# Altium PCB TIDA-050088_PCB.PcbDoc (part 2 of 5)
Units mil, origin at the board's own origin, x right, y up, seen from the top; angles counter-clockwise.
Board outline 8500 x 7000 mil, 8 copper layers (Top Layer, Layer 1 - GND, Signal Layer 2, Layer 3 - GND, Layer 4 - Power, Signal Layer 5, Layer 6 - GND, Bottom Layer), stack 61.6 mil thick; 537 components, 169 nets, 1427 pads, 1411 vias.
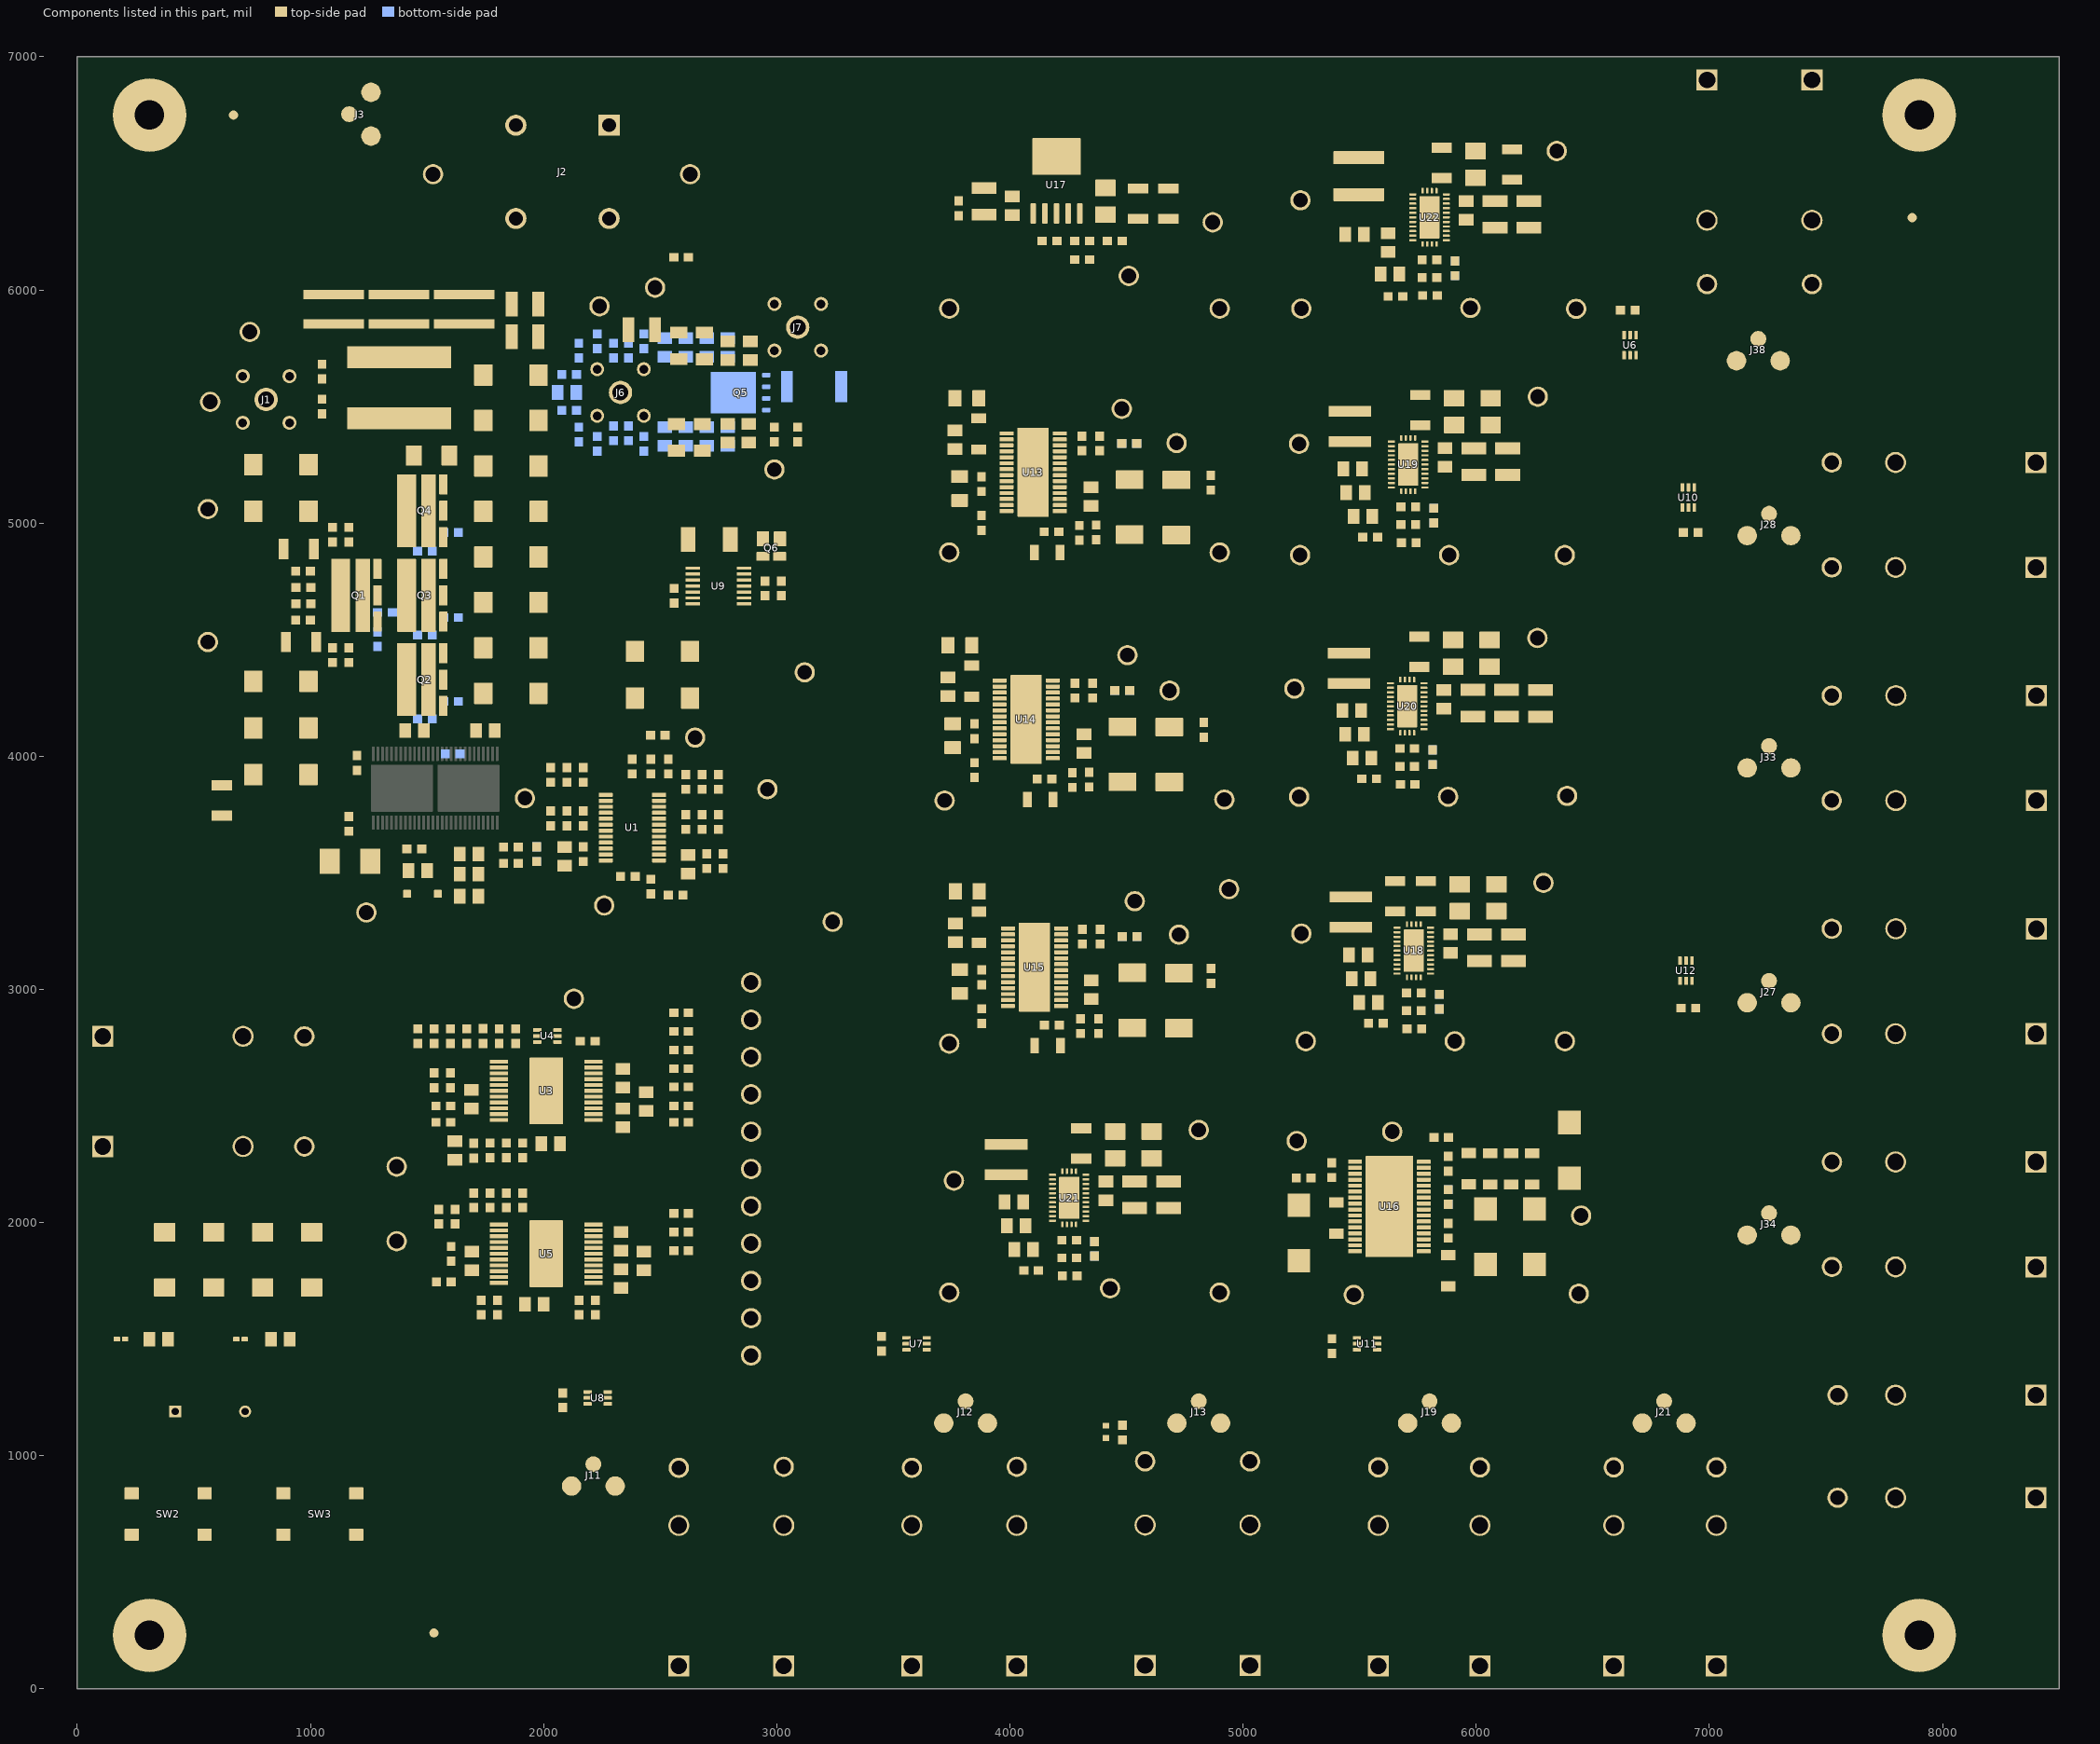
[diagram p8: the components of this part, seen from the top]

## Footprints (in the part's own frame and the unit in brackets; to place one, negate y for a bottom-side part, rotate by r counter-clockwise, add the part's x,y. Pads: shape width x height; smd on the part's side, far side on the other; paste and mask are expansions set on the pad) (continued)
DAP0032F-MFG [mm]
  rrect22% 1.5x0.45 smd paste+0 mask+0: 1(-3.75,4.875) 2(-3.75,4.225) 3(-3.75,3.575) 4(-3.75,2.925) 5(-3.75,2.275) 6(-3.75,1.625) 7(-3.75,0.975) 8(-3.75,0.325) 9(-3.75,-0.325) 10(-3.75,-0.975) 11(-3.75,-1.625) 12(-3.75,-2.275) 13(-3.75,-2.925) 14(-3.75,-3.575) 15(-3.75,-4.225) 16(-3.75,-4.875) 17(3.75,-4.875) 18(3.75,-4.225) 19(3.75,-3.575) 20(3.75,-2.925) 21(3.75,-2.275) 22(3.75,-1.625) 23(3.75,-0.975) 24(3.75,-0.325) 25(3.75,0.325) 26(3.75,0.975) 27(3.75,1.625) 28(3.75,2.275) 29(3.75,2.925) 30(3.75,3.575) 31(3.75,4.225) 32(3.75,4.875)
  rrect2% 5.2x11 smd paste-1000 mask-1000: 33(0,0)
  silkscreen extent -5.2,-5.55 3.1,5.55, body extent -4.6,-5.8 4.6,5.8, height 0.25
DCK0006A-MFG [mm]
  rrect25% 0.9x0.4 smd paste-1000 mask+0: 1(-1.1,0.65) 2(-1.1,0) 3(-1.1,-0.65) 4(1.1,-0.65) 5(1.1,0) 6(1.1,0.65)
  silkscreen extent -2.23,-1.07 0.27,1.07, body extent -1.65,-1.33 1.65,1.33, height 0.25
DCQ0006A-MFG [mm]
  rrect17% 2.2x0.6 smd paste-1000 mask+0: 1(-3.1,2.54) 2(-3.1,1.27) 3(-3.1,0) 4(-3.1,-1.27) 5(-3.1,-2.54)
  rrect3% 4x5.3 smd paste-1000 mask-1000: 6(3.1,0)
  silkscreen extent -4.9,-3.27 1.78,3.27, body extent -4.3,-3.37 5.2,3.37, height 0.25
DQH0008A [mm] "TI"
  rrect39% 0.91x0.51 smd paste-0.05 mask-0.05: 1(-2.795,1.905) 2(-2.795,0.635) 3(-2.795,-0.635) 4(-2.795,-1.905) 5(2.795,-1.905) 6(2.795,-0.635) 7(2.795,0.635) 8(2.795,1.905)
  rrect9% 1.14x1.23 on Bottom Paste: 9(-1.06,-1.43) 9(-1.06,0) 9(-1.06,1.43) 9(0.28,-1.43) 9(0.28,0) 9(0.28,1.43) 9(1.62,-1.43) 9(1.62,0) 9(1.62,1.43)
  rrect2% 4.02x4.42 on Bottom Solder: 9(0.38,0)
  rrect2% 4.93x4.52 smd paste-3 mask-3: 9(0.786,0)
  silkscreen extent -3.18,-2.68 3.18,2.68, body extent -3.05,-2.55 3.05,2.55, height 1.06
FCC_disclaimer [mil]
Fiducial10-20 [mm]
  round 1 smd mask+0.5: 1(0,0)
  Top Layer keep-out circle w1.178: c0,0 r0.5
FP-1929517_HDR2-MFG [mm]
  round 2.3 hole 1.5 paste-2539.97 mask+0: 1(-5.18,7.82) 2(4.98,7.82) 2(4.98,-2.34)
  rect 2.3x2.3 hole 1.5 paste-2539.97 mask+0: 1(-5.18,-2.34)
  body extent -10.36,-11.2 10.36,11.2, height 0.25
FP-430182050816_SMT_SW_6MM2_6MM2-MFG [mm]
  rrect8% 1.55x1.3 smd paste+0 mask+0: 1(-3.975,2.25) 2(-3.975,-2.25) 3(3.975,2.25) 4(3.975,-2.25)
  silkscreen extent -5.42,-3.2 3.2,3.2, body extent -4.85,-3.3 4.85,3.3, height 0.25
FP-60312102114405_CONN_SMA-MFG [mm]
  round 1.73 smd paste+0 mask+0: 1(0,0)
  round 2.115 smd paste+0 mask+0: 2(-2.38,-2.385) 3(2.38,-2.385)
  Top Layer region: 3.555,-3.56 3.555,3.56 1.205,3.56 1.205,1.652 1.823,0.927 2.045,0 1.823,-0.927 1.205,-1.652 1.205,-1.652 1.205,-3.56
  Top Layer region: -3.555,-3.56 -3.555,3.56 -1.205,3.56 -1.205,1.652 -1.823,0.927 -2.045,0 -1.823,-0.927 -1.205,-1.652 -1.205,-1.652 -1.205,-3.56
  silkscreen extent -0.83,-3.27 0.83,3.27, body extent -3.66,-3.66 3.66,3.66, height 0.25
FP-A6TN-1104_PTH_SW_7MM50_4MM48-MFG [mm]
  rect 1.3x1.3 hole 0.8 paste-2539.97 mask+0: 1(0,-3.81)
  round 1.3 hole 0.8 paste-2539.97 mask+0: 2(0,3.81)
  body extent -2.59,-4.56 2.59,4.56, height 0.25
FP-BLM18EG221SN1D_0603-MFG [mm]
  rrect15% 0.65x0.7 smd paste+0 mask+0: 1(-0.675,0) 2(0.675,0)
  silkscreen extent -0.87,-0.72 0.87,0.72, body extent -1.1,-0.58 1.1,0.58, height 0.25
FP-BZT52B13-E3-08_SOD123-MFG [mm] "Recommended Land Pattern"
  rrect12% 0.85x0.85 smd paste+0 mask+0: 1(1.675,0) 2(-1.675,0)
  silkscreen extent -2.77,-0.85 1.43,0.85, body extent -2.2,-0.95 2.2,0.95, height 0.25
FP-C1206C225K4RAC7800_1206-MFG [mm] "Recommended Land Pattern"
  rrect11% 0.95x1.7 smd paste+0 mask+0: 1(-1.4,0) 2(1.4,0)
  silkscreen extent -0.55,-0.9 0.55,0.9, body extent -2,-1 2,1, height 0.25
FP-EPC7019GC_FSMD-G-MFG [mm]
  rrect11% 2.184x0.914 smd paste+0 mask+0: 1(2.87,2.286) 2(-2.87,2.286) 5(0,2.286)
  rrect5% 7.95x2.057 smd paste+0 mask+0: 3(0,-1.714)
  rrect6% 7.95x1.575 smd paste+0 mask+0: 4(0,0.686)
  silkscreen extent -4.08,-3.25 4.77,3.25, body extent -4.18,-2.96 4.18,2.96, height 0.25
FP-FBG04N08ACH_FSMD-A-MFG [mm]
  rrect10% 0.965x1.422 smd paste+0 mask+0: 1(-1.118,0.901) 3(-1.118,-0.901)
  rrect7% 1.6x1.346 smd paste+0 mask+0: 2(0.8,0.927) 4(0.8,-0.927)
  silkscreen extent -2.26,-1.97 1.7,1.97, body extent -1.81,-1.81 1.81,1.81, height 0.25
FP-SK5C0A_SMA-MFG [mil]
  rrect6% 67.5x86 smd paste+0 mask+0: 1(-76.25,0) 2(76.25,0)
  silkscreen extent -137,-52 28,52, body extent -114,-56 114,56, height 10
FP-T520X158M2R5ATE015_2917-MFG [mm]
  rrect5% 1.99x2.33 smd paste+0 mask+0: 1(-3.01,0) 2(3.01,0)
  silkscreen extent -3.8,-2.3 4.9,2.3, body extent -4.13,-2.42 4.13,2.42, height 0.25
FP-T521D157M020ATE050_2917-MFG [mm]
  rrect5% 1.99x2.33 smd paste+0 mask+0: 1(3.01,0) 2(-3.01,0)
  silkscreen extent -4.9,-2.3 3.8,2.3, body extent -4.13,-2.42 4.13,2.42, height 0.25
FP-TRME107K020R0035_2917-MFG [mm]
  rrect5% 2x3 smd paste+0 mask+0: 1(-3,0) 2(3,0)
  silkscreen extent -3.75,-2.25 4.87,2.25, body extent -4.1,-2.35 4.1,2.35, height 0.25
HFT0022A-C01-MFG [mm]
  rrect23% 2x0.435 smd paste+0 mask+0: 1(-5.145,3.175) 2(-5.145,2.54) 3(-5.145,1.905) 4(-5.145,1.27) 5(-5.145,0.635) 6(-5.145,0) 7(-5.145,-0.635) 8(-5.145,-1.27) 9(-5.145,-1.905) 10(-5.145,-2.54) 11(-5.145,-3.175) 12(5.145,-3.175) 13(5.145,-2.54) 14(5.145,-1.905) 15(5.145,-1.27) 16(5.145,-0.635) 17(5.145,0) 18(5.145,0.635) 19(5.145,1.27) 20(5.145,1.905) 21(5.145,2.54) 22(5.145,3.175)
  rrect3% 3.62x7.29 smd paste-1000 mask+0: 23(0,0)
  silkscreen extent -6.83,-3.97 3.23,3.97, body extent -6.24,-4.07 6.24,4.07, height 0.25
IEC_HotSurface_Medium [mil]
  silkscreen extent -217,-188 217,188
Keystone5010 [mil] "Keystone Multipurpose loops"
  round 87 hole 63: 1(0,0)
  silkscreen extent -70,-70 70,70, body extent -63,-63 63,62, height 319
Keystone5011 [mil] "Keystone Multipurpose loops"
  round 87 hole 63: 1(0,0)
  silkscreen extent -70,-70 70,70, body extent -63,-63 63,62, height 319
Keystone5012 [mil] "Keystone Multipurpose loops"
  round 87 hole 63: 1(0,0)
  silkscreen extent -70,-70 70,70, body extent -63,-63 63,62, height 319
Keystone_1902C [mil] "Hex Standoff, 4-40 threaded, nylon"
  round 1 on Mech4: 0(0,0)
  body extent -145,-126 146,126, height 501
"NY PMS 440 0025 PH" [mm] "4-40 nylon screw and mounting hole"
  round 8 hole 3.2: 1(0,0)
  body extent -3.3,-3.3 3.3,3.3, height 2.69
PW0014A-MFG [mm]
  rrect29% 1.6x0.35 smd paste-1000 mask+0: 1(-2.8,1.95) 2(-2.8,1.3) 3(-2.8,0.65) 4(-2.8,0) 5(-2.8,-0.65) 6(-2.8,-1.3) 7(-2.8,-1.95) 8(2.8,-1.95) 9(2.8,-1.3) 10(2.8,-0.65) 11(2.8,0) 12(2.8,0.65) 13(2.8,1.3) 14(2.8,1.95)
  silkscreen extent -4.33,-2.55 2.25,2.55, body extent -3.7,-2.8 3.7,2.8, height 0.25
PW0024A-MFG [mm]
  rrect22% 1.5x0.45 smd paste+0 mask+0: 1(-2.9,3.575) 2(-2.9,2.925) 3(-2.9,2.275) 4(-2.9,1.625) 5(-2.9,0.975) 6(-2.9,0.325) 7(-2.9,-0.325) 8(-2.9,-0.975) 9(-2.9,-1.625) 10(-2.9,-2.275) 11(-2.9,-2.925) 12(-2.9,-3.575) 13(2.9,-3.575) 14(2.9,-2.925) 15(2.9,-2.275) 16(2.9,-1.625) 17(2.9,-0.975) 18(2.9,-0.325) 19(2.9,0.325) 20(2.9,0.975) 21(2.9,1.625) 22(2.9,2.275) 23(2.9,2.925) 24(2.9,3.575)
  silkscreen extent -4.37,-3.95 1.78,3.95, body extent -3.75,-4.2 3.75,4.2, height 0.25
PWP0028A-MFG [mm]
  rrect22% 1.5x0.45 smd paste+0 mask+0: 1(-2.9,4.225) 2(-2.9,3.575) 3(-2.9,2.925) 4(-2.9,2.275) 5(-2.9,1.625) 6(-2.9,0.975) 7(-2.9,0.325) 8(-2.9,-0.325) 9(-2.9,-0.975) 10(-2.9,-1.625) 11(-2.9,-2.275) 12(-2.9,-2.925) 13(-2.9,-3.575) 14(-2.9,-4.225) 15(2.9,-4.225) 16(2.9,-3.575) 17(2.9,-2.925) 18(2.9,-2.275) 19(2.9,-1.625) 20(2.9,-0.975) 21(2.9,-0.325) 22(2.9,0.325) 23(2.9,0.975) 24(2.9,1.625) 25(2.9,2.275) 26(2.9,2.925) 27(2.9,3.575) 28(2.9,4.225)
  rrect3% 3.4x9.7 smd paste-1000 mask-1000: 29(0,0)
  silkscreen extent -4.35,-5.25 2.25,5.25, body extent -3.75,-5.15 3.75,5.15, height 0.25
RNP0030A-MFG [mm]
  rrect40% 0.75x0.25 smd paste+0 mask+0: 1(-1.825,2.5) 2(-1.825,2) 3(-1.825,1.5) 4(-1.825,1) 5(-1.825,0.5) 6(-1.825,0) 7(-1.825,-0.5) 8(-1.825,-1) 9(-1.825,-1.5) 10(-1.825,-2) 11(-1.825,-2.5) 16(1.825,-2.5) 17(1.825,-2) 18(1.825,-1.5) 19(1.825,-1) 20(1.825,-0.5) 21(1.825,0) 22(1.825,0.5) 23(1.825,1) 24(1.825,1.5) 25(1.825,2) 26(1.825,2.5)
  rrect40% 0.25x0.6 smd paste+0 mask+0: 12(-0.75,-2.9) 13(-0.25,-2.9) 14(0.25,-2.9) 15(0.75,-2.9) 27(0.75,2.9) 28(0.25,2.9) 29(-0.25,2.9) 30(-0.75,2.9)
  rrect5% 2.2x4.6 smd paste-1000 mask+0: 31(0,0)
  silkscreen extent -2.9,-3.05 2.05,3.05, body extent -2.3,-3.3 2.3,3.3, height 0.25
SMB [mil] "Molded Diode, 2-Leads, Body 5.4x3.6mm, IPC Medium Density, based on OnSemi component dimensions"
  rect 85x107.99 smd: 1(-87.01,0) 2(87.01,0)
  silkscreen extent -155,-82 125,82, body extent -106,-71 106,71, height 91
Tek_131-5031-00 [mil] "Tektronix cold nose probe"
  round 100 hole 68: 1(0,0)
  round 60 hole 38: 2(-100,100) 3(-100,-100) 4(100,-100) 5(100,100)
  silkscreen extent -92,-93 94,94, body extent -206,-206 206,206, height 351
TI_Stacked_Overlay_Small [mil]
  silkscreen extent -418,-98 418,98
WEEE_Minimum [mil] "WEEElie bin"
  silkscreen extent -95,-172 99,104
XAL1010 [mm] "COILCRAFT"
  rect 2.38x11.31 smd: 1(-3.325,0) 2(3.325,0)
  silkscreen extent -5.3,-6 5.3,6, body extent -5.25,-5.9 5.25,5.9, height 10
XAL5030 [mil] "Coilcraft XAL5030 12/12/11"
  rect 46x183 smd: 1(-65,0) 2(65,0)
  silkscreen extent -108,-112 108,112, body extent -108,-112 108,112, height 122
XAL6030 [mm] "Coilcraft recommended land pattern Document 887-4 Revised 01/14/18"
  rrect7% 1.43x5.5 smd: 1(-2.019,0) 2(2.019,0)
  body extent -3.28,-3.38 3.28,3.38, height 3.11

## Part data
C1 C2 C3 C4 C5 C44 C45 C46 C47: library part CMP-0093169-1, "150µF Molded Tantalum Polymer Capacitor 20V 2917 (7343 Metric) 50mOhm @ 100kHz", Digikey Part Number=399-19581-1-ND, Leakage Current=300uA, Manufacturer=Kemet, Mouser Part Number=80-T521D157M020ATE50, Operating Temperature Range="-55°C to +105°C", Tolerance_%=20%, ValueDisplayed=150uF
C6 C7 C8: library part CMP-0009175-2, "CAP, CERM, 10 uF, 25 V, +/- 10%, X7R, AEC-Q200 Grade 1, 1210", Cap_Case=1210, Manufacturer=MuRata, Supplier Part Number 1=490-4798-1-ND, TempCo=X7R, Tolerance_%=10%, Value1=Unknown, Value2=25V, ValueDisplayed=10uF
C9 C10 C11 C12 C13 C14 C15 C16 C18 C109: library part CMP-0084679-1, "CAP, CERM, 0.1 µF, 25 V,+/- 10%, X7R, AEC-Q200 Grade 1, 0603", Cap_Case=0603, Manufacturer=MuRata, TempCo=X7R, Tolerance_%=10%, Value2=25V, ValueDisplayed=0.1µF
C17 C19 C28 C29 C43 C62 C63 C64 C65 C66 C67: library part CMP-0079630-1, "CAP, CERM, 1 µF, 16 V,+/- 10%, X7R, AEC-Q200 Grade 1, 0805", Cap_Case=0805, Manufacturer=Kemet, Supplier Part Number 1=399-6930-1-ND, TempCo=X7R, Tolerance_%=10%, Value2=16V, ValueDisplayed=1µF
C20: library part CMP-0006880-4, "CAP, CERM, 150 pF, 50 V, +/- 5%, C0G/NP0, 0603", Cap_Case=0603, Manufacturer=Kemet, Supplier Part Number 1=399-1063-1-ND, TempCo=C0G/NP0, Tolerance_%=5%, Value1=Unknown, Value2=50V, ValueDisplayed=150pF
C21: library part CMP-0007275-4, "CAP, CERM, 56 pF, 100 V, +/- 5%, C0G/NP0, 0603", Cap_Case=0603, Manufacturer=MuRata, Supplier Part Number 1=490-1345-1-ND, TempCo=C0G/NP0, Tolerance_%=5%, Value1=Unknown, Value2=100V, ValueDisplayed=56pF
C22: library part CMP-0006901-4, "CAP, CERM, 0.022 uF, 50 V, +/- 10%, X7R, 0603", Cap_Case=0603, Manufacturer=Kemet, Supplier Part Number 1=399-1280-1-ND, TempCo=X7R, Tolerance_%=10%, Value1=Unknown, Value2=50V, ValueDisplayed=0.022uF
C23: library part CMP-0007142-4, "CAP, CERM, 0.47 uF, 25 V, +/- 10%, X7R, AEC-Q200 Grade 1, 0603", Cap_Case=0603, Manufacturer=MuRata, Supplier Part Number 1=490-4776-1-ND, TempCo=X7R, Tolerance_%=10%, Value1=Unknown, Value2=25V, ValueDisplayed=0.47uF
C24: library part CMP-0007460-5, "CAP CER 0.056UF 50V X7R 0603", Cap_Case=0603, Manufacturer="Kyocera AVX", TempCo=X7R, Value2=50V, ValueDisplayed=0.056uF
C25: library part CMP-0080734-1, "CAP, CERM, 470 pF, 10 V,+/- 5%, C0G/NP0, 0603", Cap_Case=0603, Manufacturer="Wurth Elektronik", Supplier Part Number 1=732-7756-1-ND, TempCo=C0G/NP0, Tolerance_%=5%, Value2=10V, ValueDisplayed=470pF
C26 C27 C31 C80 C81 C82 C83 C87 C88 C89 C90: library part CMP-0085980-1, "CAP, CERM, 1 µF, 35 V,+/- 10%, X7R, 0805", Cap_Case=0805, Manufacturer=MuRata, TempCo=X7R, Tolerance_%=10%, Value2=35V, ValueDisplayed=1µF
C30: library part CMP-0079095-1, "CAP, CERM, 0.1 µF, 50 V,+/- 10%, X7R, AEC-Q200 Grade 1, 0603", Cap_Case=0603, Manufacturer=AVX, Supplier Part Number 1=478-3540-1-ND, TempCo=X7R, Tolerance_%=10%, Value2=50V, ValueDisplayed=0.1µF
C32 C33 C34 C35 C36 C37 C38 C39 C40 C41: library part CMP-0122762-1, "Cap Tant Polymer 1500uF 2.5V X CASE 20% (7.3 X 4.3 X 4mm) SMD 7343-43, X 15 mOhm 105°C T/R", Digikey Part Number=399-T520X158M2R5ATE015CT-ND, Leakage Current=375uA, Manufacturer=KEMET, Mouser Part Number=80-T520X158M2R5ATE15, Operating Temperature Range="-55°C to +105°C", Tolerance_%=20%, ValueDisplayed=1.5mF
C42 C95: library part CMP-0006979-5, "CAP, CERM, 0.1 uF, 25 V, +/- 10%, X7R, 0603", Cap_Case=0603, Manufacturer=Kemet, Supplier Part Number 1=399-5345-1-ND, TempCo=X7R, Tolerance_%=10%, Value1=Unknown, Value2=25V, ValueDisplayed=0.1uF
C48 C49 C50: library part CMP-0081783-1, "CAP, CERM, 22 µF, 16 V,+/- 10%, X7R, 1210", Cap_Case=1210, Manufacturer=Samsung, Supplier Part Number 1=1276-3394-1-ND, TempCo=X7R, Tolerance_%=10%, Value2=16V, ValueDisplayed=22µF
C51 C52 C53 C54: library part CMP-0008687-2, "CAP, CERM, 10 uF, 10 V, +/- 10%, X7R, 1206", Cap_Case=1206, Manufacturer=TDK, Supplier Part Number 1=445-14793-1-ND, TempCo=X7R, Tolerance_%=10%, Value1="0.002454 ohm", Value2=10V, ValueDisplayed=10uF
C55 C56 C57 C58: library part CMP-0007690-2, "CAP, CERM, 4.7 uF, 10 V, +/- 10%, X7R, 0805", Cap_Case=0805, Manufacturer="Wurth Elektronik", Supplier Part Number 1=710-885012207025, TempCo=X7R, Tolerance_%=10%, Value1=Unknown, Value2=10V, ValueDisplayed=4.7uF
C59 C60 C61: library part CMP-0008317-2, "CAP, CERM, 2.2 uF, 10 V, +/- 10%, X7R, 0805", Cap_Case=0805, Manufacturer=MuRata, Supplier Part Number 1=490-1696-1-ND, TempCo=X7R, Tolerance_%=10%, Value1="0.006 ohm", Value2=10V, ValueDisplayed=2.2uF
C68 C69 C70 C71 C72 C73 C84 C92 C93 C94 C96 C97 C98: library part CMP-0006946-4, "CAP, CERM, 0.47 uF, 10 V, +/- 10%, X7R, 0603", Cap_Case=0603, Manufacturer=Kemet, Supplier Part Number 1=399-4923-1-ND, TempCo=X7R, Tolerance_%=10%, Value1=Unknown, Value2=10V, ValueDisplayed=0.47uF
C74 C75 C76 C77 C78 C79: library part CMP-0064931-4, "CAP, CERM, 0.1 uF, 10 V,+/- 10%, X7R, 0603", Cap_Case=0603, Manufacturer="Wurth Elektronik", Supplier Part Number 1=732-7939-1-ND, TempCo=X7R, Tolerance_%=10%, Value1=Unknown, Value2=10V, ValueDisplayed=0.1uF
C85: library part CMP-0007750-2, "CAP, CERM, 1.5 uF, 10 V, +/- 10%, X7R, 0805", Cap_Case=0805, Manufacturer=Kemet, Supplier Part Number 1=399-4931-1-ND, TempCo=X7R, Tolerance_%=10%, Value1="0.009 ohm", Value2=10V, ValueDisplayed=1.5uF
C86 C91: library part CMP-0007674-2, "CAP, CERM, 0.47 uF, 16 V, +/- 5%, X7R, 0805", Cap_Case=0805, Manufacturer=AVX, Supplier Part Number 1=478-3774-1-ND, TempCo=X7R, Tolerance_%=5%, Value1="0.011 ohm", Value2=16V, ValueDisplayed=0.47uF
C99 C100 C101 C102 C118 C119: library part CMP-0096895-1, "Cap Tant Solid 100uF 20V E CASE 10% (7.3 X 4.1 X 4.3mm) SMD 7343-43 0.035 Ohm 125°C T/R", Digikey Part Number=478-11130-1-ND, Leakage Current=15uA, Manufacturer="KYOCERA AVX", Mouser Part Number=581-TRME107K020R0035, Operating Temperature Range="-55°C to +125°C", Tolerance_%=10%, ValueDisplayed=100uF
C103 C106 C121 C134: library part CMP-0007039-5, "CAP, CERM, 0.1 uF, 25 V, +/- 10%, X7R, 0603", Cap_Case=0603, Manufacturer=TDK, Supplier Part Number 1=445-1316-1-ND, TempCo=X7R, Tolerance_%=10%, Value1=Unknown, Value2=25V, ValueDisplayed=0.1uF
C104 C107 C111 C115 C122 C136: library part CMP-0084376-1, "CAP, Tantalum Polymer, 10 µF, 10 V,+/- 20%, 0.08 ohm, 3216-18 SMD", Cap_Case=3216-18, Manufacturer=Kemet, Tolerance_%=20%, Value1="0.08 ohm", Value2=10V, ValueDisplayed=10µF
C105 C108 C123: library part CMP-0006832-5, "CAP, CERM, 0.1 uF, 25 V, +/- 10%, X7R, 0603", Cap_Case=0603, Manufacturer="Wurth Elektronik", Supplier Part Number 1=710-885012206071, TempCo=X7R, Tolerance_%=10%, Value1=Unknown, Value2=25V, ValueDisplayed=0.1uF
C110 C113 C135: library part CMP-0124122-1, "2.2 µF ±10% 16V Ceramic Capacitor X7R 1206 (3216 Metric)", Digikey Part Number=399-C1206C225K4RAC7800CT-ND, Manufacturer=KEMET, Mouser Part Number=80-C1206C225K4R, Operating Temperature Range="-55°C to +125°C", TempCo=15%, Temperature Characteristic=X7R, Tolerance_%=10%, ValueDisplayed=2.2uF
C112 C116 C137: library part CMP-0007564-2, "CAP, CERM, 4700 pF, 25 V, +/- 5%, C0G/NP0, 0805", Cap_Case=0805, Manufacturer=AVX, Supplier Part Number 1=478-1332-1-ND, TempCo=C0G/NP0, Tolerance_%=5%, Value1="0.556 ohm", ValueDisplayed=4700pF
C114 C117 C138: library part CMP-0860521-1, "CAP, CERM, 4.7 µF, 25 V,+/- 10%, X7R, 1206", Cap_Case=1206, Manufacturer=AVX, TempCo=X7R, Tolerance_%=10%, Value2=25V, ValueDisplayed=4.7µF
C120: library part CMP-0006976-5, "CAP, CERM, 1000 pF, 50 V, +/- 10%, X7R, 0603", Cap_Case=0603, Manufacturer=Kemet, Supplier Part Number 1=399-5348-1-ND, TempCo=X7R, Tolerance_%=10%, Value1=Unknown, Value2=50V, ValueDisplayed=1000pF
C124 C128 C129 C130 C131 C133: library part CMP-0008813-2, "CAP, CERM, 4.7 uF, 16 V, +/- 10%, X7R, AEC-Q200 Grade 1, 1206", Cap_Case=1206, Manufacturer=MuRata, Supplier Part Number 1=490-6065-1-ND, TempCo=X7R, Tolerance_%=10%, Value1=Unknown, Value2=16V, ValueDisplayed=4.7uF
C125 C126 C127: library part CMP-0012656-3, "CAP, Tantalum Polymer, 150 uF, 10 V, +/- 20%, 0.005 ohm, 7343-31 SMD", Cap_Case=7.3x4.3mm, Manufacturer=Kemet, Supplier Part Number 1=399-10369-1-ND, Tolerance_%=20%, Value1="0.005 ohm", Value2=10V, ValueDisplayed=150uF
C132: library part CMP-0064985-2, "CAP, Tantalum Polymer, 220 uF, 10 V,+/- 20%, 0.018 ohm, 7343-31 SMD", Cap_Case=7343-31, Manufacturer=Kemet, Supplier Part Number 1=399-4045-1-ND, Tolerance_%=20%, Value1="0.018 ohm", Value2=10V, ValueDisplayed=220uF
C139 C147 C148 C150 C151 C168 C169 C171 C172 C173 C188 C189: library part CMP-0064938-2, "CAP, CERM, 10 uF, 25 V,+/- 10%, X7R, 1210", Cap_Case=1210, Manufacturer="Wurth Elektronik", Supplier Part Number 1=732-7729-1-ND, TempCo=X7R, Tolerance_%=10%, Value1=Unknown, Value2=25V, ValueDisplayed=10uF
C140 C145 C146 C166 C167 C187: library part CMP-0007695-2, "CAP CER 0.47UF 25V X7R 0805", Cap_Case=0805, Manufacturer="Samsung Electro-Mechanics", TempCo=X7R, Tolerance_%=10%, Value2=25V, ValueDisplayed=0.47uF
C141 C142 C153 C154 C157 C175 C178 C191 C192: library part CMP-0009154-2, "CAP, CERM, 22 uF, 16 V, +/- 20%, X7R, AEC-Q200 Grade 1, 1210", Cap_Case=1210_280, Manufacturer=TDK, Supplier Part Number 1=445-5723-1-ND, TempCo=X7R, Tolerance_%=20%, Value1="0.002582 ohm", Value2=16V, ValueDisplayed=22uF
C143 C155 C156 C158 C159 C176 C177 C179 C180 C193: library part CMP-0011556-2, "CAP, TA, 100 uF, 6.3 V, +/- 20%, 0.015 ohm, SMD", Cap_Case=3528-21, Manufacturer=Kemet, Supplier Part Number 1=399-5306-1-ND, Tolerance_%=20%, Value1="0.015 ohm", Value2=6.3V, ValueDisplayed=100uF
C144: library part CMP-0007127-4, "CAP, CERM, 470 pF, 50 V, +/- 5%, C0G/NP0, AEC-Q200 Grade 1, 0603", Cap_Case=0603, Manufacturer=MuRata, Supplier Part Number 1=490-4965-1-ND, TempCo=C0G/NP0, Tolerance_%=5%, Value1=Unknown, Value2=50V, ValueDisplayed=470pF
C149 C152 C170 C174 C190: library part CMP-0007695-2, "CAP CER 0.47UF 25V X7R 0805", Cap_Case=0805, Manufacturer=Kemet, Supplier Part Number 1=399-6974-2-ND, TempCo=X7R, ValueDisplayed=0.47uF
C160 C161 C181 C182 C194: library part CMP-0007867-2, "CAP, CERM, 2.2 uF, 16 V, +/- 10%, X7R, 0805", Cap_Case=0805, Manufacturer=TDK, Supplier Part Number 1=445-1420-1-ND, TempCo=X7R, Tolerance_%=10%, Value1="0.0049 ohm", Value2=16V, ValueDisplayed=2.2uF
C162 C163 C183 C184: library part CMP-0007211-4, "CAP, CERM, 36 pF, 50 V, +/- 5%, C0G/NP0, 0603", Cap_Case=0603, Manufacturer=MuRata, Supplier Part Number 1=490-1416-1-ND, TempCo=C0G/NP0, Tolerance_%=5%, Value1=Unknown, Value2=50V, ValueDisplayed=36pF
C164 C165 C185 C186 C196: library part CMP-0007729-2, "CAP, CERM, 1 uF, 16 V, +/- 10%, X7R, 0805", Cap_Case=0805, Manufacturer=Kemet, Supplier Part Number 1=399-1284-1-ND, TempCo=X7R, Tolerance_%=10%, Value1="0.015 ohm", Value2=16V, ValueDisplayed=1uF
C195: library part CMP-0007171-4, "CAP, CERM, 100 pF, 50 V, +/- 5%, C0G/NP0, 0603", Cap_Case=0603, Manufacturer=MuRata, Supplier Part Number 1=490-1427-1-ND, TempCo=C0G/NP0, Tolerance_%=5%, Value1=Unknown, Value2=50V, ValueDisplayed=100pF
D1: library part CMP-0076963-2, "Diode, Superfast Rectifier, 50 V, 3 A, SMB", Manufacturer="Diodes Inc.", Value1=3A, Value2=0.9V
D2: library part CMP-0124121-1, "Diode Zener Single 13V 500mW 2-Pin SOD-123 T/R", Digikey Part Number=112-BZT52B13-E3-08CT-ND, Manufacturer=Vishay, Max Reverse Leakage Current=0.1uA, Mouser Part Number=78-BZT52B13-E3-08, Operating Temperature Range="-55°C to +150°C", Power_W=300mW
D3: library part CMP-0122761-1, "Rectifier Diode Schottky 200V 5A Automotive AEC-Q101 2-Pin SMA T/R", Digikey Part Number=4786-SK5C0ACT-ND, Forward Current=5A, Manufacturer=Good-Ark, Max Surge Forward Current=120A, Operating Temperature Range="-55°C to +150°C", Peak Reverse Current=30uA, ValueDisplayed=96pF
D4 D5: library part CMP-0067682-2, "LED, Green, SMD", Color=Green, Manufacturer=Kingbright, Power_TotalModule=75mW, Value1=0.075W, Value2=2.1V
FB1: library part CMP-0122734-1, "Chip Ferrite Bead, 0603, 220Ω @ 100MHz, 0.05Ω, 25%, 2A", Impedance At Frequency="220Ω @ 100MHz", Manufacturer=Murata, Operating Temperature Range="-55°C to +125℃", Test Frequency=100MHz, Tolerance_%=25%
FID1 FID2 FID3: library part CMP-0077181-1, "Fiducial mark.  There is nothing to buy or mount.", Manufacturer=N/A
H1 H2 H3 H4: library part CMP-0003617-1, "Machine Screw, Round, #4-40 x 1/4, Nylon, Philips panhead", Manufacturer="B&F Fastener Supply", Supplier Part Number 1=H542-ND
H5 H6 H7 H8: library part CMP-0003610-1, "Standoff, Hex, 0.5\"L #4-40 Nylon", Manufacturer=Keystone, Supplier Part Number 1=36-1902C-ND
J1 J6 J7: library part CMP-0055433-1, "Compact Probe Tip Circuit Board Test Points, TH, 25 per", Manufacturer=Tektronix, PartNumber=131-5031-00, Supplier Part Number 1=11B2822
J2: library part CMP-0078537-1, "Fixed Terminal Blocks MKDSP 10 HV/ 2-10", Current_A=76A, Manufacturer="Phoenix Contact", Voltage_V=1kV
J3 J11 J12 J13 J19 J21 J27 J28 J33 J34 J38: library part CMP-0098472-1, "SMA Connector Jack, Female Socket 50Ohm Surface Mount Solder", Dielectric Material=PTFE, Digikey Part Number=732-13837-1-ND, Frequency_Fixed=0-18GHz, Manufacturer="Wurth Electronics", Mouser Part Number=710-60312102114405, Operating Temperature Range="-65°C to +165°C"
J4 J8 J9 J10 J17 J18 J20 J25 J26 J31 J32 J37: library part CMP-0055393-3, "Standard Banana Jack, insulated, 10A, red", Manufacturer="DEM Manufacturing", Supplier Part Number 1=30M0087
J5 J14 J15 J16 J22 J23 J24 J29 J30 J35 J36 J39: library part CMP-0055389-3, "Standard Banana Jack, insulated, 10A, black", Manufacturer="DEM Manufacturing", Supplier Part Number 1=45M6896
L1: library part CMP-0060952-1, "Inductor, Shielded, Composite, 680 nH, 36 A, 0.00087 ohm, SMD", Manufacturer=Coilcraft, Supplier Part Number 1=994-XAL1010-681MEB, Value1="0.00087 ohm", Value2=36A, ValueDisplayed=680nH
L2 L3 L4: library part CMP-0061006-2, "Inductor, Shielded, Composite, 800 nH, 13 A, 0.01 ohm, AEC-Q200 Grade 1, SMD", Manufacturer=Coilcraft, Value1="0.01 ohm", Value2=13A, ValueDisplayed=800nH
L5: library part CMP-0060999-2, "Inductor, Shielded, Composite, 1.2 µH, 11.1 A, 0.01 ohm, AEC-Q200 Grade 1, SMD", Manufacturer=Coilcraft, Value1="0.01 ohm", Value2=11.1A, ValueDisplayed=1.2uH
L6: library part CMP-0061014-2, "Inductor, Shielded, Composite, 1.8 µH, 14 A, 0.01052 ohm, AEC-Q200 Grade 1, SMD", Manufacturer=Coilcraft, Value1="0.01052 ohm", Value2=14A, ValueDisplayed=1.8µH
Logo1: library part CMP-0074838-1, "Texas Instrument Corporate Signature"
Logo2: library part CMP-0074847-1, "FCC_disclaimer"
Logo3: library part CMP-0074769-1
Logo4: library part CMP-0074837-2, "IEC 61010-1 Hot Surface Warning", Manufacturer="Texas Instruments"
Q1 Q2 Q3 Q4: library part CMP-0044865-1, "MOSFET N-Channel 40 V 80A (Tc) Surface Mount 5-SMD", Digikey Part Number=4107-EPC7019GC-ND, Drain To Source Breakdown Voltage=40V, Input Capacitace At Vds="2830pF @ 20V", Manufacturer="EPC Space", Operating Temperature Range="-55°C to +150°C", Pulse Drain Current=530A
Q5: library part CMP-0000264-1, "MOSFET, N-CH, 25 V, 113 A, DQH0008A (VSON-CLIP-8)", Alternate Manufacturer=None, Manufacturer="Texas Instruments", Supplier Part Number 1=296-25321-1-ND, Value1=0.005, Value2="6.7 nC"
Q6: library part CMP-0122642-1, "Rad Hard e-GaN 40 V, 8 A, 28 mΩ Surface Mount (FSMD-A)", Input Capacitace At Vds="283pF @ 20V", Manufacturer="EPC SPACE", Operating Temperature Range="-55°C to +150°C", Pulse Drain Current=32A, Typ Forward Diode Voltage=2.5V
R1 R98 R99 R112 R117 R118 R119 R120 R127 R128 R129 R130 R137 R138: library part CMP-0023387-3, "RES, 50, 0.1%, 0.125 W, 0603", Manufacturer="Vishay Thin Film", Power_W=125mW, Supplier Part Number 1=FC0603-50BFCT-ND, TempCo="25 ppm/C", Tolerance_%=0.1%, Value2=0.125W, Value_Code=50R0, ValueDisplayed=50
R2 R22 R35 R37 R53 R68 R78 R113: library part CMP-0023392-3, "RES, 10.0 k, 0.1%, 0.0375 W, 0603", Manufacturer="Vishay Sfernice", Power_W=37.5mW, Supplier Part Number 1=PHTB-10KCT-ND, TempCo="15 ppm/C", Tolerance_%=0.1%, Value2=0.0375W, Value_Code=10k0, ValueDisplayed=10.0k
R3: library part CMP-0022138-4, "RES, 1.00 M, 1%, 0.1 W, AEC-Q200 Grade 0, 0603", Manufacturer=Vishay-Dale, Power_W=100mW, Supplier Part Number 1=541-1.00MHCT-ND, TempCo="100 ppm/C", Tolerance_%=1%, Value2=0.1W, Value_Code=1M00, ValueDisplayed=1.00M
R4: library part CMP-0023520-3, "RES, 33.0 k, 0.1%, 0.1 W, 0603", Manufacturer="Susumu Co Ltd", Power_W=100mW, Supplier Part Number 1=RG16P33.0KBCT-ND, TempCo="25 ppm/C", Tolerance_%=0.1%, Value2=0.1W, Value_Code=33k0, ValueDisplayed=33.0k
R5 R8 R10 R16 R17 R18 R19 R21 R28 R29 R30 R32 R33 R34 R36 R54 R77 R103 R111: library part CMP-0081973-1, "RES, 0, 0%, 0.25 W, AEC-Q200 Grade 0, 0603", Manufacturer=Vishay-Dale, Power_W=250mW, Supplier Part Number 1=541-2779-1-ND, Tolerance_%=0%, Value2=0.25W, Value_Code=0
R6: library part CMP-0025687-2, "RES, 10.0, 0.1%, 0.1 W, 0603", Manufacturer=Vishay-Dale, Power_W=100mW, Supplier Part Number 1=TNP10.0AACT-ND, TempCo="25 ppm/C", Tolerance_%=0.1%, Value2=0.1W, Value_Code=10R0, ValueDisplayed=10.0
R7 R55 R69: library part CMP-0024214-3, "RES, 40.2 k, 0.1%, 0.1 W, 0603", Manufacturer="Yageo America", Power_W=100mW, TempCo="25 ppm/C", Tolerance_%=0.1%, Value2=0.1W, Value_Code=40k2, ValueDisplayed=40.2k
R9: library part CMP-0023416-3, "RES, 110 k, 0.1%, 0.1 W, 0603", Manufacturer="Susumu Co Ltd", Power_W=100mW, Supplier Part Number 1=RG16P110KBCT-ND, TempCo="25 ppm/C", Tolerance_%=0.1%, Value2=0.1W, Value_Code=110k
R11 R14: library part CMP-0024180-2, "RES 397K OHM 1% 1/10W 060", Manufacturer="KOA Speer Electronics, Inc.", Tolerance_%=1%, Value_Code=397k, ValueDisplayed=DNP
R12: library part CMP-0024180-2, "RES 397K OHM 1% 1/10W 060", Manufacturer="KOA Speer Electronics, Inc.", Tolerance_%=1%, Value_Code=397k
R13: library part CMP-0024283-3, "RES, 49.9 k, 0.1%, 0.1 W, 0603", Manufacturer="Yageo America", Power_W=100mW, TempCo="25 ppm/C", Tolerance_%=0.1%, Value2=0.1W, Value_Code=49k9, ValueDisplayed=49.9k
R15: library part CMP-0022711-2, "RES, 2.20, 1%, 0.1 W, 0603", Manufacturer=Panasonic, Power_W=100mW, Supplier Part Number 1=P2.2AJCT-ND, TempCo="200 ppm/C", Tolerance_%=1%, Value2=0.1W, Value_Code=2R20, ValueDisplayed=2.20
R20: library part CMP-0025805-4, "RES, 3.3, 5%, 0.1 W, AEC-Q200 Grade 0, 0603", Manufacturer=Vishay-Dale, Power_W=100mW, Supplier Part Number 1=541-3.3GCT-ND, TempCo="200 ppm/C", Tolerance_%=5%, Value2=0.1W, Value_Code=3R30, ValueDisplayed=3.3
R23 R25 R27: library part CMP-0015108-2, "RES, 0.007, 1%, 3 W, 2512 WIDE", Manufacturer="Susumu Co Ltd", Power_W=3W, Supplier Part Number 1=408-1617-1-ND, TempCo="50 ppm/C", Tolerance_%=1%, Value_Code=7L000, ValueDisplayed=0.007
R24: library part CMP-0024147-3, "RES, 35.7 k, 0.1%, 0.1 W, 0603", Manufacturer="Yageo America", Power_W=100mW, TempCo="25 ppm/C", Tolerance_%=0.1%, Value2=0.1W, Value_Code=35k7, ValueDisplayed=35.7k
R26: library part CMP-0024164-3, "RES, 37.4 k, 0.1%, 0.1 W, 0603", Manufacturer="Yageo America", Power_W=100mW, TempCo="25 ppm/C", Tolerance_%=0.1%, Value2=0.1W, Value_Code=37k4, ValueDisplayed=37.4k
R31: library part CMP-0023466-3, "RES, 2.10 k, 0.1%, 0.1 W, 0603", Manufacturer="Susumu Co Ltd", Power_W=100mW, Supplier Part Number 1=RG16P2.1KBCT-ND, TempCo="25 ppm/C", Tolerance_%=0.1%, Value2=0.1W, Value_Code=2k10, ValueDisplayed=2.10k
R38: library part CMP-0015409-2, "RES 0.062 OHM 1% 2W 2512", Manufacturer=Yageo, Supplier Part Number 1=13-PE2512FKF7W0R062LCT-ND, Tolerance_%=1%, ValueDisplayed=0.062
R39 R40 R41 R42 R43 R45 R47 R61 R63 R65: library part CMP-0025823-4, "RES, 510, 5%, 0.1 W, AEC-Q200 Grade 0, 0603", Manufacturer=Vishay-Dale, Power_W=100mW, Supplier Part Number 1=541-510GCT-ND, TempCo="200 ppm/C", Tolerance_%=5%, Value2=0.1W, Value_Code=510R, ValueDisplayed=510
R44: library part CMP-0024346-2, "RES 56.9K OHM 0.5% 1/10W 0603", Tolerance_%=0.5%, Value_Code=56k9, ValueDisplayed=56.9k
R46: library part CMP-0023674-3, "RES, 118 k, 0.1%, 0.1 W, 0603", Manufacturer="Yageo America", Power_W=100mW, TempCo="25 ppm/C", Tolerance_%=0.1%, Value2=0.1W, Value_Code=118k
R48: library part CMP-0024051-3, "RES, 29.4 k, 0.1%, 0.1 W, 0603", Manufacturer="Yageo America", Power_W=100mW, TempCo="25 ppm/C", Tolerance_%=0.1%, Value2=0.1W, Value_Code=29k4, ValueDisplayed=29.4k
R49 R64: library part CMP-0024333-2, "RES 54.2K OHM 0.1% 0.21W 0603", Manufacturer="Vishay Dale", Tolerance_%=0.1%, Value_Code=54k2, ValueDisplayed=54.2k
R50: library part CMP-0024201-2, "RES, 3.61 k, 0.1%, 0.1 W, 0603", Manufacturer="Yageo America", Power_W=100mW, TempCo="25 ppm/C", Tolerance_%=0.1%, Value2=0.1W, Value_Code=3k61, ValueDisplayed=3.61k
R51: library part CMP-0024039-3, "RES, 28.7 k, 0.1%, 0.1 W, 0603", Manufacturer="Yageo America", Power_W=100mW, TempCo="25 ppm/C", Tolerance_%=0.1%, Value2=0.1W, Value_Code=28k7, ValueDisplayed=28.7k
R52: library part CMP-0023664-2, "RES 111K OHM 0.1% 1/10W 0603", Manufacturer="KOA Speer Electronics, Inc.", Tolerance_%=0.1%, Value_Code=111k
R56 R71: library part CMP-0023563-3, "RES, 49.9 k, 0.1%, 0.1 W, 0603", Manufacturer="Susumu Co Ltd", Power_W=100mW, Supplier Part Number 1=RG16P49.9KBCT-ND, TempCo="25 ppm/C", Tolerance_%=0.1%, Value2=0.1W, Value_Code=49k9, ValueDisplayed=49.9k
R57 R72: library part CMP-0025493-3, "RES, 65.7 k, 0.5%, 0.1 W, 0603", Manufacturer="Yageo America", Power_W=100mW, TempCo="50 ppm/C", Tolerance_%=0.5%, Value2=0.1W, Value_Code=65k7, ValueDisplayed=65.7k
R58 R73: library part CMP-0023328-4, "RES, 976 k, 1%, 0.1 W, 0603", Manufacturer=Yageo, Power_W=100mW, Supplier Part Number 1=311-976KHRCT-ND, TempCo="100 ppm/C", Tolerance_%=1%, Value2=0.1W, Value_Code=976k
R59 R74: library part CMP-0023928-2, "RES SMD 20K OHM 0.1% 1/10W 0603", Manufacturer="Panasonic Electronic Components", Tolerance_%=0.1%, Value_Code=20k
R60: library part CMP-0023431-3, "RES, 1.30 k, 0.1%, 0.1 W, 0603", Manufacturer="Susumu Co Ltd", Power_W=100mW, Supplier Part Number 1=RG16P1.3KBCT-ND, TempCo="25 ppm/C", Tolerance_%=0.1%, Value2=0.1W, Value_Code=1k30, ValueDisplayed=1.30k
R62 R136: library part CMP-0024127-2, "RES 34K OHM 0.1% 1/10W 0603", Manufacturer="KOA Speer Electronics, Inc.", Tolerance_%=0.1%, Value_Code=34k
R66: library part CMP-0024247-2, "RES SMD 44.2KOHM 0.1% 1/10W 0603", Manufacturer=Yageo, Tolerance_%=0.1%, Value_Code=44k2, ValueDisplayed=44.2k
R67: library part CMP-0024461-3, "RES, 75.0 k, 0.1%, 0.1 W, 0603", Manufacturer="Yageo America", Power_W=100mW, TempCo="25 ppm/C", Tolerance_%=0.1%, Value2=0.1W, Value_Code=75k0, ValueDisplayed=75.0k
R70: library part CMP-0024283-3, "RES SMD 49.3KOHM 0.1% 1/10W 0603", Manufacturer=Yageo, Tolerance_%=0.1%, Value_Code=49k3, ValueDisplayed=49.3k
R75: library part CMP-0023868-3, "RES SMD 1.1K OHM 0.1% 1/10W 0603", Manufacturer="Panasonic Electronic Components", Tolerance_%=0.1%, Value_Code=1k1, ValueDisplayed=1.1k
R76: library part CMP-0016527-2, "RES, 0.3, 1%, 1 W, 2010", Manufacturer="Stackpole Electronics Inc", Power_W=1W, Supplier Part Number 1=CSRN2010FKR300CT-ND, TempCo="250 ppm/C", Tolerance_%=1%, Value_Code=R300, ValueDisplayed=0.3
R79 R80 R81 R82 R100 R101: library part CMP-0023161-5, "RES, 4.99, 1%, 0.1 W, 0603", Manufacturer=Yageo, Power_W=100mW, Supplier Part Number 1=311-4.99HRCT-ND, TempCo="200 ppm/C", Tolerance_%=1%, Value_Code=4R99, ValueDisplayed=4.99
R83 R84 R102 R106: library part CMP-0023167-5, "RES, 51.0 k, 1%, 0.1 W, 0603", Manufacturer=Yageo, Power_W=100mW, Supplier Part Number 1=311-51.0KHRCT-ND, TempCo="100 ppm/C", Tolerance_%=1%, Value2=0.1W, Value_Code=51k0, ValueDisplayed=51.0k
R85 R86: library part CMP-0024147-3, "RES SMD 36.5KOHM 0.1% 1/10W 0603", Manufacturer="Panasonic Electronic Components", Tolerance_%=0.1%, Value_Code=36k5, ValueDisplayed=36.5k
R87 R88 R105: library part CMP-0065342-2, "RES, 10.0, 1%, .5 W, AEC-Q200 Grade 0, 0805", Manufacturer=Panasonic, Power_W=500mW, Supplier Part Number 1=P16861CT-ND, TempCo="200 ppm/C", Tolerance_%=1%, Value2=.5W, Value_Code=10R0, ValueDisplayed=10.0
R89 R94 R109: library part CMP-0023653-3, "RES, 10.0 k, 0.1%, 0.1 W, 0603", Manufacturer="Yageo America", Power_W=100mW, TempCo="25 ppm/C", Tolerance_%=0.1%, Value_Code=10k0, ValueDisplayed=10.0k
R90 R92: library part CMP-0023441-3, "RES, 15.0 k, 0.1%, 0.1 W, 0603", Manufacturer="Susumu Co Ltd", Power_W=100mW, Supplier Part Number 1=RG16P15.0KBCT-ND, TempCo="25 ppm/C", Tolerance_%=0.1%, Value2=0.1W, Value_Code=15k0, ValueDisplayed=15.0k
R91 R93 R108: library part CMP-0023710-3, "RES, 12.0 k, 0.1%, 0.1 W, 0603", Manufacturer="Yageo America", Power_W=100mW, TempCo="25 ppm/C", Tolerance_%=0.1%, Value_Code=12k0, ValueDisplayed=12.0k
R95 R96 R110: library part CMP-0025433-3, "RES, 5.05 k, 0.5%, 0.1 W, 0603", Manufacturer="Yageo America", TempCo="50 ppm/C", Tolerance_%=0.5%, Value2=0.1W, Value_Code=5k05, ValueDisplayed=5.05k
R97: library part CMP-0024179-2, "RES, 392, 0.1%, 0.1 W, 0603", Manufacturer="Yageo America", Power_W=100mW, TempCo="25 ppm/C", Tolerance_%=0.1%, Value2=0.1W, Value_Code=392R, ValueDisplayed=392
R104: library part CMP-0023840-3, "RES SMD 18.7KOHM 0.1% 1/10W 0603", Manufacturer="Panasonic Electronic Components", Tolerance_%=0.1%, Value_Code=18k7, ValueDisplayed=18.7k
R107: library part CMP-0024552-2, "RES, 9.20 k, 0.1%, 0.1 W, 0603", Manufacturer="Yageo America", Power_W=100mW, TempCo="25 ppm/C", Tolerance_%=0.1%, Value2=0.1W, Value_Code=9k20, ValueDisplayed=9.20k
R114: library part CMP-0024193-2, "RES, 3.20 k, 0.1%, 0.1 W, 0603", Manufacturer="Yageo America", Power_W=100mW, TempCo="25 ppm/C", Tolerance_%=0.1%, Value2=0.1W, Value_Code=3k20, ValueDisplayed=3.20k
R115: library part CMP-0021519-3, "RES, 1.00 k, 1%, 0.125 W, AEC-Q200 Grade 0, 0805", Manufacturer=Panasonic, Power_W=125mW, Supplier Part Number 1=P1.00KCCT-ND, TempCo="100 ppm/C", Tolerance_%=1%, Value2=0.125W, Value_Code=1k00, ValueDisplayed=1.00k
R116: library part CMP-0021253-3, "RES, 422, 1%, 0.125 W, AEC-Q200 Grade 0, 0805", Manufacturer=Vishay-Dale, Power_W=125mW, Supplier Part Number 1=541-422CCT-ND, TempCo="100 ppm/C", Tolerance_%=1%, Value2=0.125W, Value_Code=422R, ValueDisplayed=422
R121 R122 R131 R132: library part CMP-0024307-2, "RES 50.5K OHM 0.1% 0.21W 0603", Manufacturer="Vishay Dale", Tolerance_%=0.1%, Value_Code=50k5, ValueDisplayed=50.5k
R123 R124 R133 R134 R140: library part CMP-0022364-4, "RES, 38.3 k, 1%, 0.1 W, AEC-Q200 Grade 0, 0603", Manufacturer=Vishay-Dale, Power_W=100mW, Supplier Part Number 1=541-38.3KHCT-ND, TempCo="100 ppm/C", Tolerance_%=1%, Value2=0.1W, Value_Code=38k3, ValueDisplayed=38.3k
R125 R126 R135: library part CMP-0024010-3, "RES SMD 261K OHM 0.1% 1/10W 0603", Manufacturer="Panasonic Electronic Components", Tolerance_%=0.1%, Value_Code=261k
R139: library part CMP-0024307-2, "RES 50K OHM 0.1% 1/10W 0603", Manufacturer=Yageo, Tolerance_%=0.1%, Value_Code=50k
R141: library part CMP-0023960-3, "RES, 22.1 k, 0.1%, 0.1 W, 0603", Manufacturer="Yageo America", Power_W=100mW, TempCo="25 ppm/C", Tolerance_%=0.1%, Value2=0.1W, Value_Code=22k1, ValueDisplayed=22.1k
SW1: library part CMP-0086077-1, "Dip Switch SPST 1 Position Through Hole Slide (Standard) Actuator 25mA 24VDC", CurrentRating_mA=25mA, Manufacturer="Omron Electronics Inc-EMC Div"
SW2 SW3: library part CMP-0097324-1, "Switch Tactile N.O. SPST Round Button Gull Wing 0.05A 12VDC 1000000Cycles 1.57N SMD Reel", Coil Resistance_ohm=100mΩ, Contact Current Rating=50mA, Digikey Part Number=732-7005-1-ND, Manufacturer="Wurth Electronics", Mouser Part Number=710-430182050816, Operating Force=160gf, Operating Temperature Range="-40°C to +85°C"
TP1 TP2 TP3 TP4 TP5 TP8 TP9 TP18 TP19 TP20 TP21 TP22 TP23 TP24 TP25 TP26 TP27 TP28 TP29 TP30 TP31 TP32 TP38 TP39 TP47 TP52 TP63 TP70 TP71 TP72 TP73 TP84 TP85 TP86 TP87 TP96 TP97: library part CMP-0055149-2, "Test Point, Multipurpose, White, TH", Color=White, Manufacturer="Keystone Electronics", PartNumber=5012, Supplier Part Number 1=36-5012-ND
TP6 TP7 TP16 TP33 TP34 TP35 TP36 TP37 TP48 TP49 TP50 TP51 TP53 TP54 TP62 TP66 TP67 TP68 TP69 TP80 TP81 TP82 TP83 TP94 TP95: library part CMP-0055147-2, "Test Point, Multipurpose, Red, TH", Color=Red, Manufacturer="Keystone Electronics", PartNumber=5010, Supplier Part Number 1=36-5010-ND
TP10 TP11 TP12 TP13 TP14 TP15 TP17 TP40 TP41 TP42 TP43 TP44 TP45 TP46 TP55 TP56 TP57 TP58 TP59 TP60 TP61 TP64 TP65 TP74 TP75 TP76 TP77 TP78 TP79 TP88 TP89 TP90 TP91 TP92 TP93 TP98 TP99 TP100: library part CMP-0055148-2, "Test Point, Multipurpose, Black, TH", Color=Black, Manufacturer="Keystone Electronics", PartNumber=5011, Supplier Part Number 1=36-5011-ND
U1: library part CMP-0094375-1, "Radiation-Hardened 2 MHz Current Mode PWM Controllers in Space Enhanced Plastic", Manufacturer="Texas Instruments", Max Supply Voltage=14V, Min Supply Voltage=4V, Nominal Supply Current=6.25-14mA, Operating Temperature Range="-55°C to +125°C", Part Number=TPS7H5006MPWSEP, Switching Frequency=100-2000MHz
U3 U5: library part CMP-0097863-4, "Radiation-Hardeness-Assured, 14-V, 4-Channel Sequencer", Manufacturer="Texas Instruments", Max Supply Voltage=14V, Min Supply Voltage=3V, Nominal Supply Current=2mA, Operating Temperature Range="-55°C to +125°C"
U4 U6 U7 U8 U10 U11 U12: library part CMP-0095470-2, "Radiation-tolerant, 1.6-V to 5.5-V, 1.25-A 90-mΩ load switch", Manufacturer="Texas Instruments", Max Supply Voltage=5.5V, Min Supply Voltage=1.6V, Operating Temperature Range="-40°C to +125°C"
U9: library part CMP-0122772-1, "Radiation-tolerant six-bit inverting fixed-direction level translator with Schmitt-trigger inputs", Manufacturer="Texas Instruments", Max Supply Voltage=5.5V, Min Supply Voltage=1.2V, Nominal Supply Current=2uA, Operating Temperature Range="-55°C to +125°C"
U13 U14 U15: library part CMP-0096731-1, "1.5-A, Ultra-Low Noise, High PSRR Radiation Hardened LDO", Dropout Voltage=1168mV, Manufacturer="Texas Instruments", Max Supply Voltage=7V, Min Supply Voltage=850mV, Nominal Supply Current=19mA, Operating Temperature Range="-55°C to +125°C", Output Voltage=0.4-5.5V
U16: library part CMP-0095960-3, "Radiation-Tolerant 3-A DDR Termination Regulator, HTSSOP32", Manufacturer="Texas Instruments", Max Supply Voltage=3.5V, Min Supply Voltage=900mV, Operating Temperature Range="-55°C to +125°C", Output Voltage=0.5-1.75V
U17: library part CMP-0094005-1, "LDO Regulator Pos 1.21V to 20V 1A 6-Pin(5+Tab) SOT-223 Tube", Dropout Voltage=0.24V, Manufacturer="Texas Instruments", Max Supply Voltage=20V, Min Supply Voltage=1.45V, Mouser Part Number=595-TPS73801MDCQPSEP, Nominal Supply Current=1-35mA, Operating Temperature Range="-55°C to +125°C", Output Voltage=1.21-20V
U18 U19 U20 U21 U22: library part CMP-0091443-1, "Radiation Hardened 3.5-V to 32-V, 6-A Synchronous Step-Down Voltage Converter in Space Enhanced Plastic, WQFN30", Manufacturer="Texas Instruments", Max Supply Voltage=32V, Min Supply Voltage=3.5V, Nominal Supply Current=0.6uA, Operating Temperature Range="-55°C to +125°C", Output Voltage=1-30.4V, Switching Frequency=350-2200kHz
ZZ1: library part CMP-0003616-3
ZZ2: library part CMP-0077236-1
ZZ3: library part CMP-0077237-1
ZZ4: library part CMP-0077238-1

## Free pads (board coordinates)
  rrect33% 11.81x61.02 smd paste+0 mask+0: 1(1269.42,3715.16) 2(1289.11,3715.16) 3(1308.79,3715.16) 4(1328.48,3715.16) 5(1348.16,3715.16) 6(1367.85,3715.16) 7(1387.53,3715.16) 8(1407.22,3715.16) 9(1426.9,3715.16) 10(1446.59,3715.16) 11(1466.27,3715.16) 12(1485.96,3715.16) 13(1505.64,3715.16) 14(1525.33,3715.16) 15(1545.01,3715.16) 16(1564.7,3715.16) 17(1584.38,3715.16) 18(1604.07,3715.16) 19(1623.75,3715.16) 20(1643.44,3715.16) 21(1663.12,3715.16) 22(1682.81,3715.16) 23(1702.49,3715.16) 24(1722.18,3715.16) 25(1741.86,3715.16) 26(1761.55,3715.16) 27(1781.23,3715.16) 28(1800.92,3715.16) 29(1800.92,4010.44) 30(1781.23,4010.44) 31(1761.55,4010.44) 32(1741.86,4010.44) 33(1722.18,4010.44) 34(1702.49,4010.44) 35(1682.81,4010.44) 36(1663.12,4010.44) 37(1643.44,4010.44) 38(1623.75,4010.44) 39(1604.07,4010.44) 40(1584.38,4010.44) 41(1564.7,4010.44) 42(1545.01,4010.44) 43(1525.33,4010.44) 44(1505.64,4010.44) 45(1485.96,4010.44) 46(1466.27,4010.44) 47(1446.59,4010.44) 48(1426.9,4010.44) 49(1407.22,4010.44) 50(1387.53,4010.44) 51(1367.85,4010.44) 52(1348.16,4010.44) 53(1328.48,4010.44) 54(1308.79,4010.44) 55(1289.11,4010.44) 56(1269.42,4010.44)
  rrect2% 265.75x200.79 smd paste-39370.1 mask-39370.1: 57(1392.46,3862.8) 58(1677.89,3862.8)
